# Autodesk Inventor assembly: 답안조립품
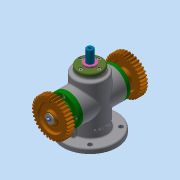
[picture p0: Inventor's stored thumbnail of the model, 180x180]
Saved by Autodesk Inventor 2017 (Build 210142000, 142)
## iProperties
Part Number: 답안조립품
Material: 일반
Document SubType Name: Assembly
Designer: mrc
Author: mrc
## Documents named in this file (17)
- C:\Users\mrc\Desktop\600606V1021\답안조립품.iam
- C:\Users\mrc\Desktop\600606V1021\본체.ipt
- C:\Users\mrc\Desktop\600606V1021\멈춤링.ipt
- C:\Users\mrc\Desktop\600606V1021\베어링 6203.ipt
- C:\Users\mrc\Desktop\600606V1021\볼트 M4.ipt
- C:\Users\mrc\Desktop\600606V1021\부시.ipt
- C:\Users\mrc\Desktop\600606V1021\스퍼기어.ipt
- C:\Users\mrc\Desktop\600606V1021\스프링와셔.ipt
- C:\Users\mrc\Desktop\600606V1021\스프링조립용 와셔.ipt
- C:\Users\mrc\Desktop\600606V1021\슬라이더.ipt
- C:\Users\mrc\Desktop\600606V1021\오일 실 17 30 8.ipt
- C:\Users\mrc\Desktop\600606V1021\커버 A.ipt
- C:\Users\mrc\Desktop\600606V1021\커버 B.ipt
- C:\Users\mrc\Desktop\600606V1021\키 4x4x12.ipt
- C:\Users\mrc\Desktop\600606V1021\편심축.ipt
- C:\Users\mrc\Desktop\600606V1021\평와셔.ipt
- C:\Users\mrc\Desktop\600606V1021\가변스프링.ipt
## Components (1 placed, 1 different names)
1. 가변스프링:1
